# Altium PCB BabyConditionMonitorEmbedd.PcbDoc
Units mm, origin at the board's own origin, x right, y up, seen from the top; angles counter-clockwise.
Board outline 160.1 x 120.1 mm, 2 copper layers (Top Layer, Bottom Layer); 0 components, 0 nets, 5 pads, 0 vias.
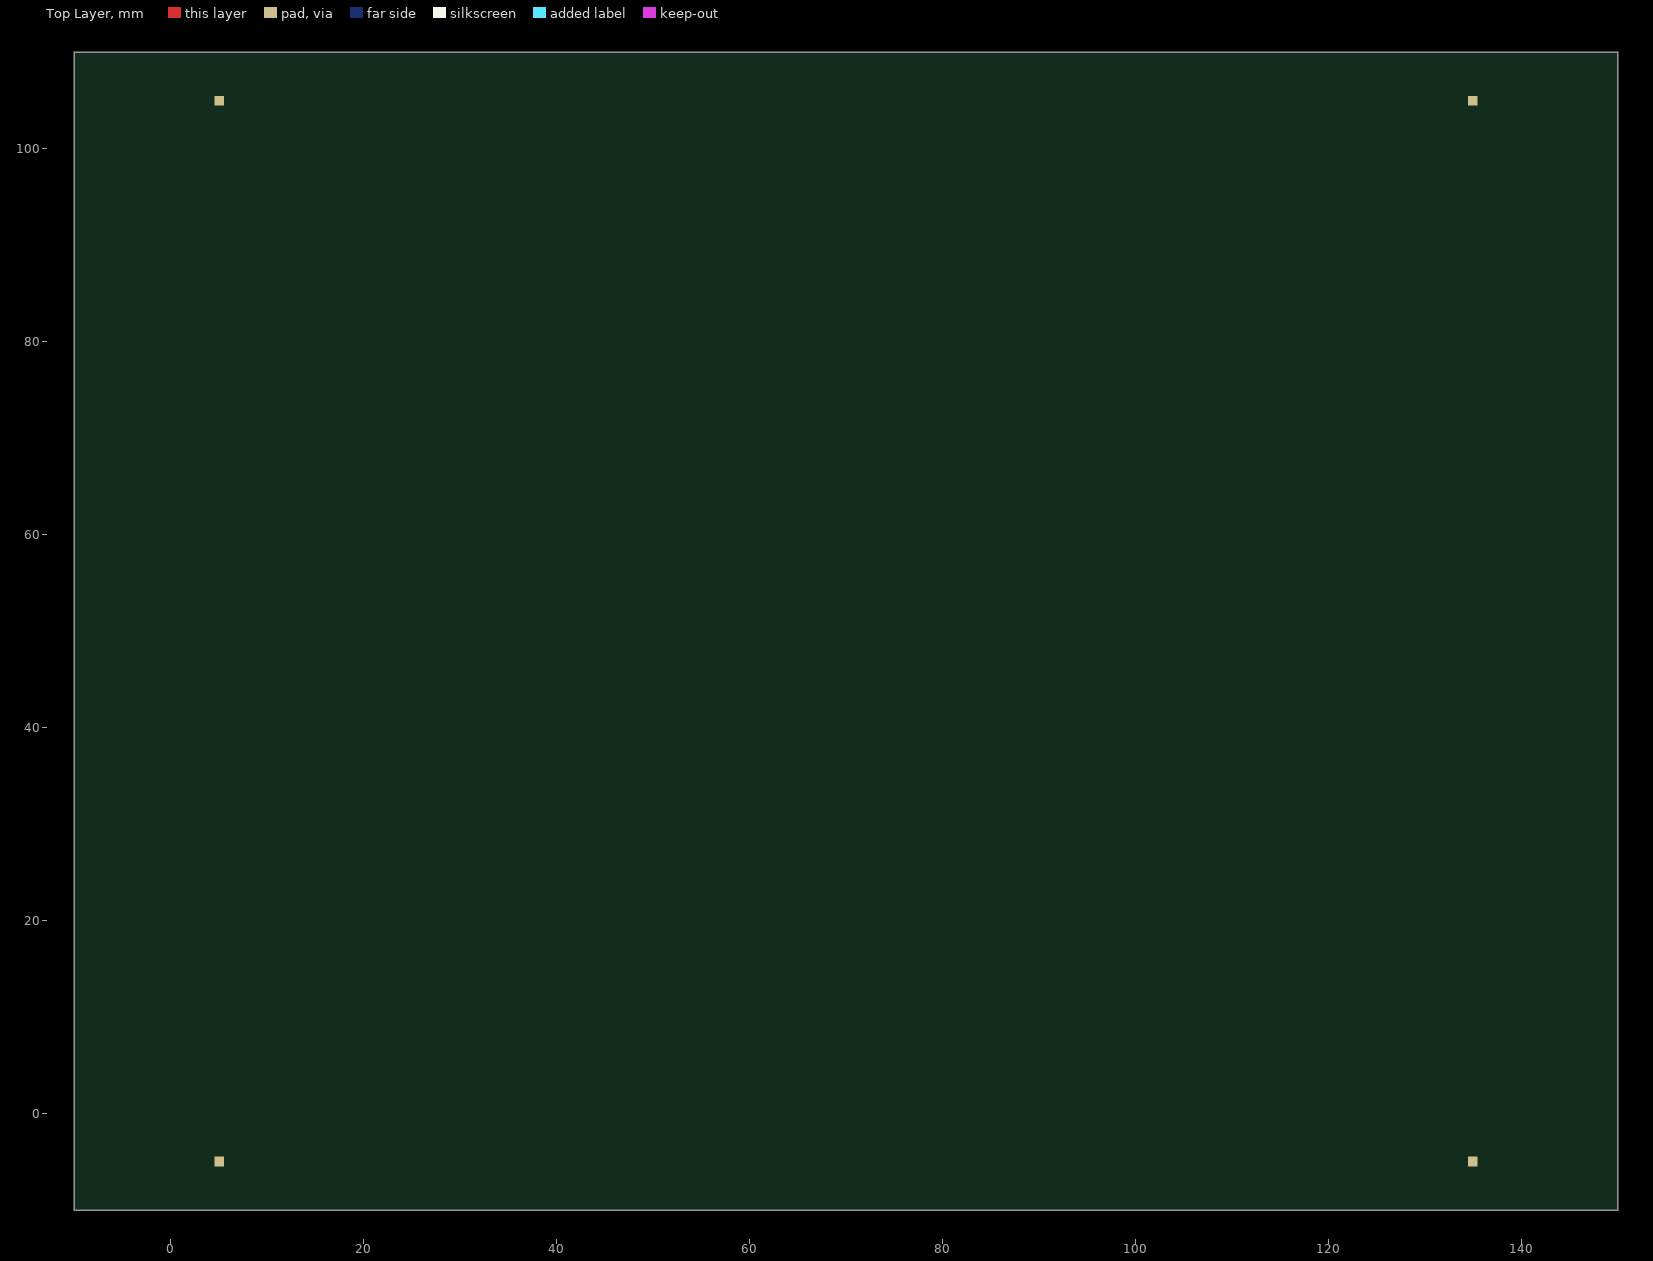
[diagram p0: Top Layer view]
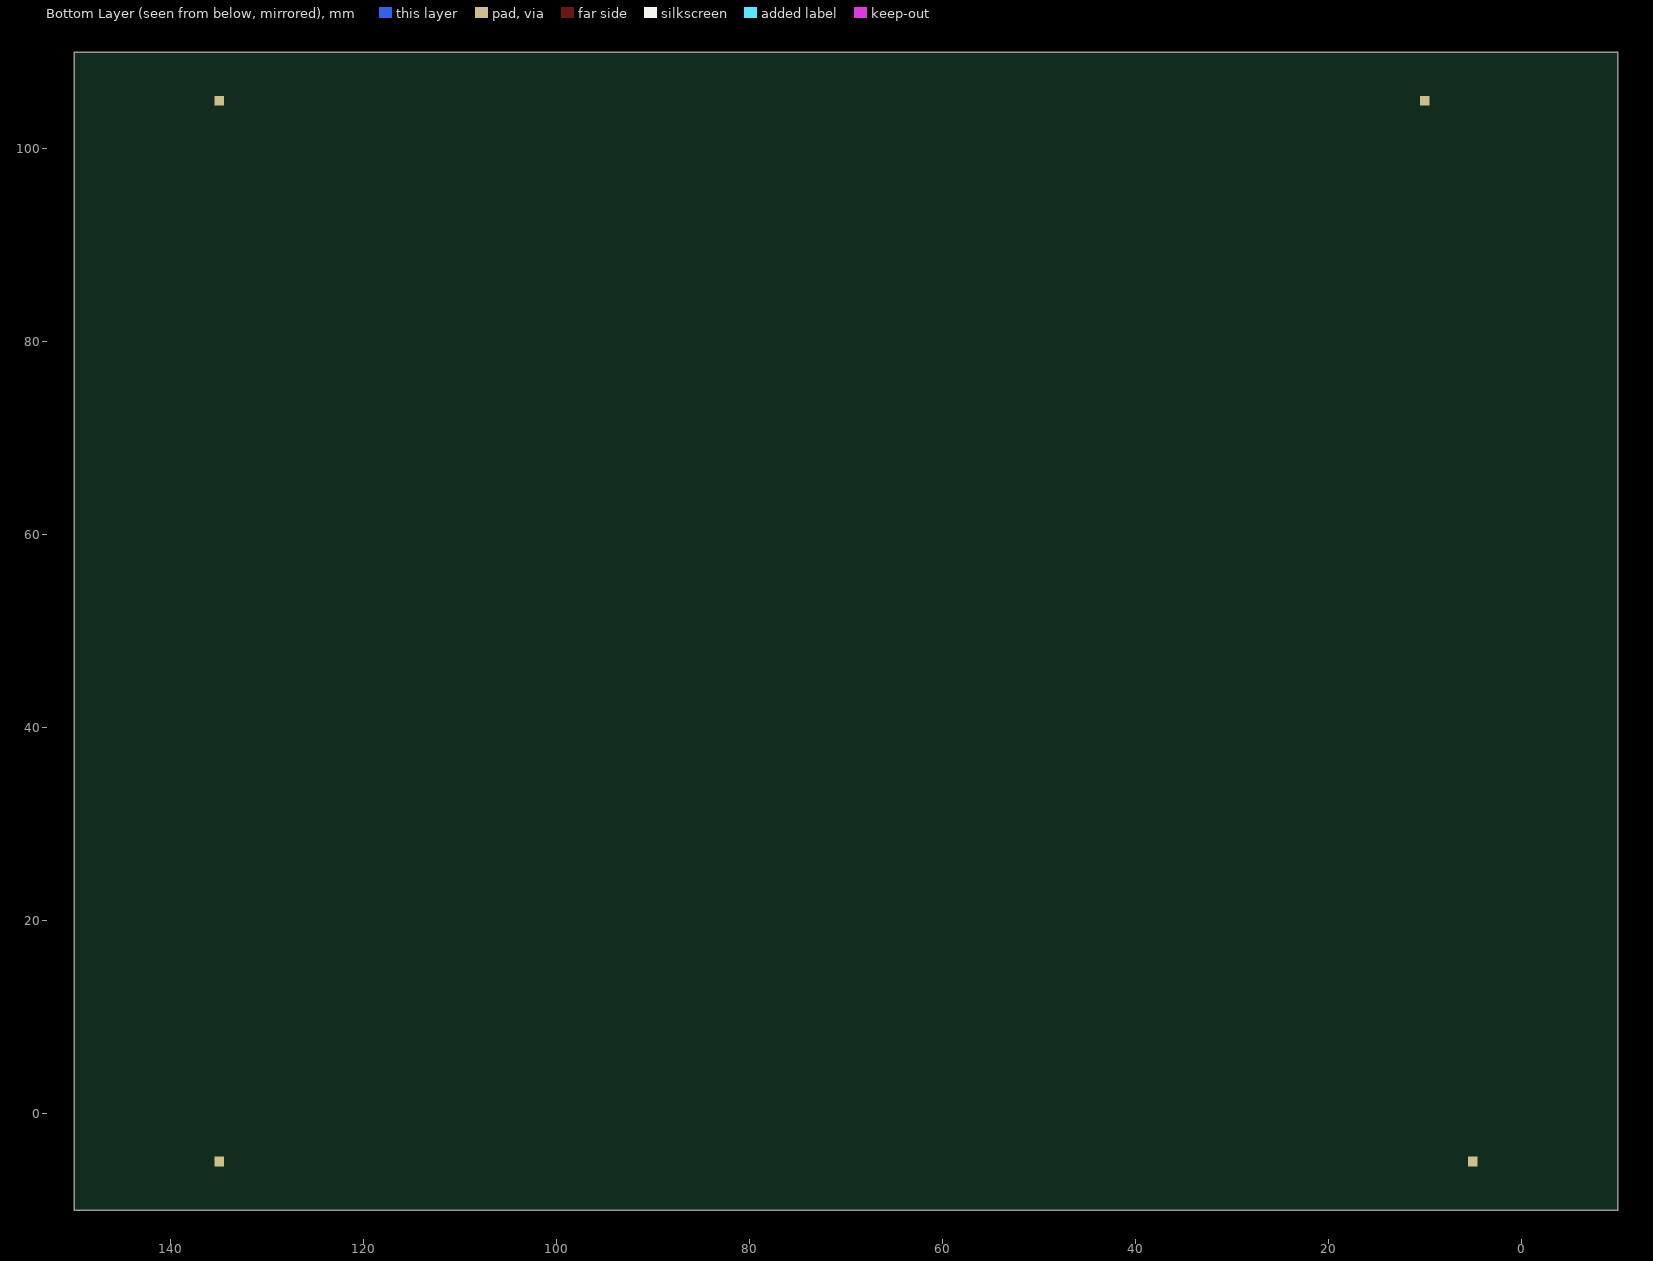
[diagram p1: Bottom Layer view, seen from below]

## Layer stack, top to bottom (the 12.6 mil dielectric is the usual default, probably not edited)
Top Solder: solder mask 0.0102, Solder Resist, Dk 3.5
Top Layer: signal copper 0.0356
Dielectric 1: dielectric 0.32, FR-4, Dk 4.8
Bottom Layer: signal copper 0.0356
Bottom Solder: solder mask 0.0102, Solder Resist, Dk 3.5

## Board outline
-10.05,-10 -10.05,110 cw(c-10,110) -10,110.05 150,110.05 cw(c150,110) 150.05,110 150.05,-10 cw(c150,-10) 149.966,-10.037 cw(c149.95,-9.989) 149.95,-10.039 -9.969,-10.039 cw(c-10,-10)

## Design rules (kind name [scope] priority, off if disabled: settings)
Clearance [All] p1: gap=0.254 ignorepadtopadclearanceinfootprint=FALSE except(0: Arc-Hole Track-Hole SMDPad-Hole THPad-Hole Via-Hole Fill-Hole Poly-Hole Region-Hole Text-Hole)
PolygonConnect [All] p1: connectstyle=Relief reliefconductorwidth=0.254 reliefentries=4 polygonreliefangle="90 Angle" airgapwidth=0.254
RoutingVias [All] p1: holewidth=0.711 width=1.27 viastyle="Through Hole" minholewidth=0.711 minwidth=1.27 maxholewidth=0.711 maxwidth=1.27
SolderMaskExpansion [All] p1: expansion=0.102
Width [All] p1: maxlimit=0.254 minlimit=0.254 preferedwidth=0.254
30 further rules are at their usual default settings.

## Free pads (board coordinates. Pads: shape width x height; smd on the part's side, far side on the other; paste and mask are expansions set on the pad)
  rect 1x1 all layers, no hole paste-1 mask+1: ""(5,-5) ""(135,-5) ""(135,105)
  rect 1x1 smd paste-1 mask+1: ""(5,105)
  rect 1x1 smd far side paste-1 mask+1: ""(10,105)

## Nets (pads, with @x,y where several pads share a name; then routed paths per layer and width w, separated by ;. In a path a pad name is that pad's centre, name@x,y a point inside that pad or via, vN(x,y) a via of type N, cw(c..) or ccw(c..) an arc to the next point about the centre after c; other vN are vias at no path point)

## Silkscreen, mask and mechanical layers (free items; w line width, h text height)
Mechanical 1:
  lines w0.1: -10,-10 -10,110 150,110 150,-10 ; -9.993,-9.989 149.95,-9.989
Mechanical 5:
  lines w0.1: -10,0 150,0 ; -10,20 150,20 ; -10,40 150,40 ; -10,60 150,60 ; -10,80 150,80 ; -10,100 150,100 ; 0,-10 0,110 ; 40,-10 40,110 ; 50,-10 50,110 ; 90,-10 90,110 ; 100,-10 100,110 ; 140,-10 140,110

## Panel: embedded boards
"BabyConditionMonitor.PcbDoc" at 100,-0.075, 5 rows x 1 columns, spacing 20 x 38.1, rotation 0
"BabyConditionMonitor.PcbDoc" at 50,-0.075, 5 rows x 1 columns, spacing 20 x 38.1, rotation 0
"BabyConditionMonitor.PcbDoc" at 0,-0.075, 5 rows x 1 columns, spacing 20 x 38.1, rotation 0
